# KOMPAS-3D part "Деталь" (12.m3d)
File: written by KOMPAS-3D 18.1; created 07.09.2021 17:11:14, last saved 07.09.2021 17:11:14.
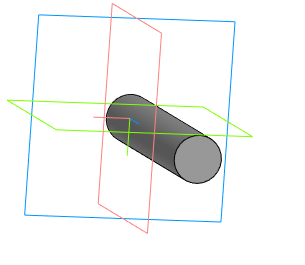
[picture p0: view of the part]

Document properties: Автор: 111; Полное имя файла: C:\Users\admin\Desktop\ffb\12.m3d

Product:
- Part/product: Деталь
    Масса: 0.061306
    source file: 12.cdw

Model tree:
1. Эскиз:1
2. Элемент выдавливания:1
     Расстояние 1 = 69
